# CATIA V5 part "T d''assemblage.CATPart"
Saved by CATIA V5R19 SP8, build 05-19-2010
Part number: T d''assemblage
Revision: ANY
Definition: UNKNOWN
Nomenclature: T d''assemblage
Source: Unknown
Bounding box of the stored display mesh (mm): x -23.5 to 23.5, y -5.5 to 5.5, z -5 to 24
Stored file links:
  D:\Documents\1_Travail\1 - ac-limoges.fr\OneDrive - ac-limoges.fr\STI2D_Turgot\2 -2I2D\3_SEQUENCE_Serre_Connectée\3- Spécificités\ITEC\EC 3 Ouverture automatique\Simulation  Ouverture Automatique\T d''assemblage.CATPart
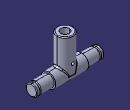
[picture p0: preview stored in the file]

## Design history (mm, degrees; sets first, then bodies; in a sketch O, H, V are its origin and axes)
Set1
  Sketch1 on face of Solid1, origin (0, 0, 25), H (1, 0, 0), V (0, 1, 0)
    circle A1 centre (0, 0) radius 6.3642
Body1 "NONE" (main body)
  Solid1: solid without history
  Pocket1: profile Sketch1, direction (0, 0, -1), length 1
  Fillet1: radius 0.5, on edge [face of Solid1 | end face of Pocket1]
